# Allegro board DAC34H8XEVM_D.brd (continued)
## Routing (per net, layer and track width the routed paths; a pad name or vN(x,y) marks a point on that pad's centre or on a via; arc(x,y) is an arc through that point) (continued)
DB3N: length 67.1
  BOTTOM w0.127: U1.P4 42.44,62.14 42.44,61.77
  BOTTOM w0.152: 42.44,61.77 42.44,59.27 37.25,54.08 36.96,54.08 36.12,53.24 35.7,53.24 35.41,53.54 35.41,54.78 35.27,54.91 35.08,54.91 34.95,54.78 34.95,53.54 34.65,53.24 34.23,53.24 33.93,53.54 33.93,54.78 33.8,54.91 33.61,54.91 33.48,54.78 33.48,53.54 33.18,53.24 32.76,53.24 32.46,53.54 32.46,54.78 32.33,54.91 32.14,54.91 32,54.78 32,53.54 31.7,53.24 31.28,53.24 30.99,53.54 30.99,54.78 30.85,54.91 30.66,54.91 30.53,54.78 30.53,53.54 30.23,53.24 29.81,53.24 29.51,53.54 29.51,54.78 29.38,54.91 29.19,54.91 29.06,54.78 29.06,53.54 28.76,53.24 28.34,53.24 28.04,53.54 28.04,54.78 27.91,54.91 27.72,54.91 27.58,54.78 27.58,53.54 27.29,53.24 26.86,53.24 26.57,53.54 26.57,54.78 26.43,54.91 26.24,54.91 26.11,54.78 26.11,53.54 25.81,53.24 25.39,53.24 25.09,53.54 25.09,54.78 24.96,54.91 24.77,54.91 24.64,54.78 24.64,53.54 24.34,53.24 23.92,53.24 23.62,53.54 23.62,54.78 23.49,54.91 23.3,54.91 23.16,54.78 23.16,53.54 22.87,53.24 22.44,53.24 22.15,53.54 22.15,54.78 22.01,54.91 21.82,54.91 21.69,54.78 21.69,53.54 21.39,53.24 20.97,53.24 20.67,53.54 20.67,54.78 20.54,54.91 20.35,54.91 20.22,54.78 20.22,53.54 19.92,53.24 19.5,53.24 18.66,54.08 18.53,54.08 15.4,57.2 14.99,57.2 v2(14.98,57.2) 14.88,57.1 13.96,57.1 13.88,57.02 J13.148
DB3P: length 67.7
  BOTTOM w0.127: 42.15,61.69 42.15,62.64 U1.N4
  BOTTOM w0.152: J13.146 13.88,57.52 13.97,57.61 14.71,57.61 14.78,57.68 15.43,57.68 15.44,57.68 v2(15.44,57.68) 15.65,57.48 15.65,57.35 18.64,54.36 18.78,54.36 19.61,53.52 19.8,53.52 19.94,53.65 19.94,54.9 20.23,55.19 20.66,55.19 20.95,54.9 20.95,53.65 21.09,53.52 21.28,53.52 21.41,53.65 21.41,54.9 21.71,55.19 22.13,55.19 22.43,54.9 22.43,53.65 22.56,53.52 22.75,53.52 22.88,53.65 22.88,54.9 23.18,55.19 23.6,55.19 23.9,54.9 23.9,53.65 24.03,53.52 24.22,53.52 24.36,53.65 24.36,54.9 24.65,55.19 25.08,55.19 25.37,54.9 25.37,53.65 25.51,53.52 25.7,53.52 25.83,53.65 25.83,54.9 26.13,55.19 26.55,55.19 26.85,54.9 26.85,53.65 26.98,53.52 27.17,53.52 27.3,53.65 27.3,54.9 27.6,55.19 28.02,55.19 28.32,54.9 28.32,53.65 28.45,53.52 28.64,53.52 28.78,53.65 28.78,54.9 29.07,55.19 29.49,55.19 29.79,54.9 29.79,53.65 29.93,53.52 30.12,53.52 30.25,53.65 30.25,54.9 30.55,55.19 30.97,55.19 31.27,54.9 31.27,53.65 31.4,53.52 31.59,53.52 31.72,53.65 31.72,54.9 32.02,55.19 32.44,55.19 32.74,54.9 32.74,53.65 32.87,53.52 33.06,53.52 33.2,53.65 33.2,54.9 33.49,55.19 33.91,55.19 34.21,54.9 34.21,53.65 34.35,53.52 34.54,53.52 34.67,53.65 34.67,54.9 34.97,55.19 35.39,55.19 35.69,54.9 35.69,53.65 35.82,53.52 36.01,53.52 36.85,54.36 37.13,54.36 42.16,59.39 42.16,61.67 42.15,61.69
DB4N: length 66.9
  BOTTOM w0.127: 41.71,61.77 41.71,62.2 U1.P3
  BOTTOM w0.152: 41.71,61.77 41.71,59.65 38.34,56.29 37.15,56.29 36.85,56.58 36.85,56.97 36.72,57.1 36.53,57.1 36.4,56.97 36.4,55.77 36.1,55.47 35.68,55.47 35.38,55.77 35.38,56.97 35.25,57.1 35.06,57.1 34.92,56.97 34.92,55.77 34.63,55.47 34.21,55.47 33.91,55.77 33.91,56.97 33.77,57.1 33.59,57.1 33.45,56.97 33.45,55.77 33.15,55.47 32.73,55.47 32.44,55.77 32.44,56.97 32.3,57.1 32.11,57.1 31.98,56.97 31.98,55.77 31.68,55.47 31.26,55.47 30.96,55.77 30.96,56.97 30.83,57.1 30.64,57.1 30.5,56.97 30.5,55.77 30.21,55.47 29.79,55.47 29.49,55.77 29.49,56.97 29.36,57.1 29.17,57.1 29.03,56.97 29.03,55.77 28.73,55.47 28.31,55.47 28.02,55.77 28.02,56.97 27.88,57.1 27.69,57.1 27.56,56.97 27.56,55.77 27.26,55.47 26.84,55.47 26.54,55.77 26.54,56.97 26.41,57.1 26.22,57.1 26.09,56.97 26.09,55.77 25.79,55.47 25.37,55.47 25.07,55.77 25.07,56.97 24.94,57.1 24.75,57.1 24.61,56.97 24.61,55.77 24.31,55.47 23.89,55.47 23.6,55.77 23.6,56.97 23.46,57.1 23.27,57.1 23.14,56.97 23.14,55.77 22.84,55.47 22.42,55.47 22.12,55.77 22.12,56.97 21.99,57.1 21.8,57.1 21.67,56.97 21.67,55.77 21.37,55.47 20.95,55.47 20.65,55.77 20.65,56.97 20.52,57.1 20.33,57.1 20.19,56.97 20.19,55.77 19.9,55.47 19.47,55.47 19.18,55.77 19.18,56.97 19.04,57.1 18.85,57.1 18.72,56.97 18.72,56.58 18.42,56.29 17.74,56.29 15.51,58.52 15.32,58.52 15.32,58.52 v2(14.96,58.52) 14.88,58.6 13.96,58.6 13.88,58.52 J13.142
DB4P: length 67.5
  BOTTOM w0.127: 41.35,61.8 41.35,62.64 U1.N3
  BOTTOM w0.152: J13.140 13.88,59.02 13.95,58.95 14.71,58.95 14.76,59 15.42,59 v2(15.42,59) 17.86,56.57 18.31,56.57 18.44,56.7 18.44,57.08 18.74,57.38 19.16,57.38 19.46,57.08 19.46,55.89 19.59,55.75 19.78,55.75 19.91,55.89 19.91,57.08 20.21,57.38 20.63,57.38 20.93,57.08 20.93,55.89 21.06,55.75 21.25,55.75 21.39,55.89 21.39,57.08 21.68,57.38 22.1,57.38 22.4,57.08 22.4,55.89 22.54,55.75 22.73,55.75 22.86,55.89 22.86,57.08 23.16,57.38 23.58,57.38 23.88,57.08 23.88,55.89 24.01,55.75 24.2,55.75 24.33,55.89 24.33,57.08 24.63,57.38 25.05,57.38 25.35,57.08 25.35,55.89 25.48,55.75 25.67,55.75 25.81,55.89 25.81,57.08 26.1,57.38 26.52,57.38 26.82,57.08 26.82,55.89 26.96,55.75 27.15,55.75 27.28,55.89 27.28,57.08 27.58,57.38 28,57.38 28.3,57.08 28.3,55.89 28.43,55.75 28.62,55.75 28.75,55.89 28.75,57.08 29.05,57.38 29.47,57.38 29.77,57.08 29.77,55.89 29.9,55.75 30.09,55.75 30.23,55.89 30.23,57.08 30.52,57.38 30.94,57.38 31.24,57.08 31.24,55.89 31.38,55.75 31.56,55.75 31.7,55.89 31.7,57.08 32,57.38 32.42,57.38 32.71,57.08 32.71,55.89 32.85,55.75 33.04,55.75 33.17,55.89 33.17,57.08 33.47,57.38 33.89,57.38 34.19,57.08 34.19,55.89 34.32,55.75 34.51,55.75 34.65,55.89 34.65,57.08 34.94,57.38 35.36,57.38 35.66,57.08 35.66,55.89 35.79,55.75 35.98,55.75 36.12,55.89 36.12,57.08 36.42,57.38 36.84,57.38 37.13,57.08 37.13,56.7 37.27,56.57 38.23,56.57 41.43,59.77 41.43,61.72 41.35,61.8
DB5N: length 67
  BOTTOM w0.127: 40.78,61.43 40.94,61.59 U1.P2
  BOTTOM w0.152: 40.78,61.43 40.08,60.73 38.06,60.73 36.82,59.49 35.28,59.49 34.93,59.14 34.93,58.26 34.63,57.96 34.21,57.96 33.92,58.26 33.92,59.71 33.78,59.84 33.59,59.84 33.46,59.71 33.46,58.26 33.16,57.96 32.74,57.96 32.44,58.26 32.44,59.71 32.31,59.84 32.12,59.84 31.99,59.71 31.99,58.26 31.69,57.96 31.27,57.96 30.97,58.26 30.97,59.71 30.84,59.84 30.65,59.84 30.51,59.71 30.51,58.26 30.21,57.96 29.79,57.96 29.5,58.26 29.5,59.71 29.36,59.84 29.17,59.84 29.04,59.71 29.04,58.26 28.74,57.96 28.32,57.96 28.02,58.26 28.02,59.71 27.89,59.84 27.7,59.84 27.57,59.71 27.57,58.26 27.27,57.96 26.85,57.96 26.55,58.26 26.55,59.71 26.42,59.84 26.23,59.84 26.09,59.71 26.09,58.26 25.8,57.96 25.37,57.96 25.08,58.26 25.08,59.71 24.94,59.84 24.75,59.84 24.62,59.71 24.62,58.26 24.32,57.96 23.9,57.96 23.6,58.26 23.6,59.71 23.47,59.84 23.28,59.84 23.15,59.71 23.15,58.26 22.85,57.96 22.43,57.96 22.13,58.26 22.13,59.71 22,59.84 21.81,59.84 21.67,59.71 21.67,58.26 21.38,57.96 20.95,57.96 20.66,58.26 20.66,59.71 20.52,59.84 20.33,59.84 20.2,59.71 20.2,58.26 19.9,57.96 19.48,57.96 19.18,58.26 19.18,59.71 19.05,59.84 18.86,59.84 18.73,59.71 18.73,58.26 18.43,57.96 18.01,57.96 17.71,58.26 17.71,58.77 17.58,58.9 17.46,58.9 16.11,60.25 15.82,60.25 v2(15.57,59.99) 15.52,60.05 14.94,60.05 14.89,60.1 13.96,60.1 13.88,60.02 J13.136
DB5P: length 67.3
  BOTTOM w0.127: 40.54,61.77 40.54,62.64 U1.N2
  BOTTOM w0.152: 40.54,61.77 40.54,61.58 39.97,61.01 37.95,61.01 36.7,59.77 35.16,59.77 34.65,59.25 34.65,58.38 34.52,58.24 34.33,58.24 34.2,58.38 34.2,59.82 33.9,60.12 33.48,60.12 33.18,59.82 33.18,58.38 33.05,58.24 32.86,58.24 32.72,58.38 32.72,59.82 32.42,60.12 32,60.12 31.71,59.82 31.71,58.38 31.57,58.24 31.38,58.24 31.25,58.38 31.25,59.82 30.95,60.12 30.53,60.12 30.23,59.82 30.23,58.38 30.1,58.24 29.91,58.24 29.78,58.38 29.78,59.82 29.48,60.12 29.06,60.12 28.76,59.82 28.76,58.38 28.63,58.24 28.44,58.24 28.3,58.38 28.3,59.82 28.01,60.12 27.58,60.12 27.29,59.82 27.29,58.38 27.15,58.24 26.96,58.24 26.83,58.38 26.83,59.82 26.53,60.12 26.11,60.12 25.81,59.82 25.81,58.38 25.68,58.24 25.49,58.24 25.36,58.38 25.36,59.82 25.06,60.12 24.64,60.12 24.34,59.82 24.34,58.38 24.21,58.24 24.02,58.24 23.88,58.38 23.88,59.82 23.59,60.12 23.16,60.12 22.87,59.82 22.87,58.38 22.73,58.24 22.54,58.24 22.41,58.38 22.41,59.82 22.11,60.12 21.69,60.12 21.39,59.82 21.39,58.38 21.26,58.24 21.07,58.24 20.94,58.38 20.94,59.82 20.64,60.12 20.22,60.12 19.92,59.82 19.92,58.38 19.79,58.24 19.6,58.24 19.46,58.38 19.46,59.82 19.17,60.12 18.74,60.12 18.45,59.82 18.45,58.38 18.31,58.24 18.12,58.24 17.99,58.38 17.99,58.88 17.69,59.18 17.58,59.18 16.23,60.53 v2(15.14,60.53) 15.06,60.45 13.95,60.45 13.88,60.52 J13.134
DB6N: length 67
  BOTTOM w0.127: U1.P1 40.13,62.24 39.85,62.51 39.1,62.51 39.09,62.5 39.06,62.5
  BOTTOM w0.152: J13.130 13.88,61.52 13.96,61.6 14.77,61.6 v2(15.01,61.37) 16.15,61.37 16.36,61.57 17.15,61.57 17.45,61.87 17.45,62.4 17.58,62.53 17.77,62.53 17.9,62.4 17.9,60.9 18.2,60.6 18.62,60.6 18.92,60.9 18.92,62.4 19.05,62.53 19.24,62.53 19.38,62.4 19.38,60.9 19.67,60.6 20.09,60.6 20.39,60.9 20.39,62.4 20.53,62.53 20.72,62.53 20.85,62.4 20.85,60.9 21.15,60.6 21.57,60.6 21.87,60.9 21.87,62.4 22,62.53 22.19,62.53 22.32,62.4 22.32,60.9 22.62,60.6 23.04,60.6 23.34,60.9 23.34,62.4 23.47,62.53 23.66,62.53 23.8,62.4 23.8,60.9 24.09,60.6 24.51,60.6 24.81,60.9 24.81,62.4 24.95,62.53 25.13,62.53 25.27,62.4 25.27,60.9 25.57,60.6 25.99,60.6 26.28,60.9 26.28,62.4 26.42,62.53 26.61,62.53 26.74,62.4 26.74,60.9 27.04,60.6 27.46,60.6 27.76,60.9 27.76,62.4 27.89,62.53 28.08,62.53 28.22,62.4 28.22,60.9 28.51,60.6 28.93,60.6 29.23,60.9 29.23,62.4 29.36,62.53 29.55,62.53 29.69,62.4 29.69,60.9 29.99,60.6 30.41,60.6 30.7,60.9 30.7,62.4 30.84,62.53 31.03,62.53 31.16,62.4 31.16,60.9 31.46,60.6 31.88,60.6 32.18,60.9 32.18,62.4 32.31,62.53 32.5,62.53 32.63,62.4 32.63,60.9 32.93,60.6 33.35,60.6 33.65,60.9 33.65,62.4 33.78,62.53 33.97,62.53 34.11,62.4 34.11,60.9 34.41,60.6 34.83,60.6 35.12,60.9 35.12,61.44 35.26,61.57 36.96,61.57 37.89,62.5 39.06,62.5
DB6P: length 67
  BOTTOM w0.127: U1.N1 40.14,63.02 39.88,62.76 39.18,62.76 39.17,62.78 39.06,62.78
  BOTTOM w0.152: 39.06,62.78 37.77,62.78 36.84,61.85 35.14,61.85 34.84,61.55 34.84,61.02 34.71,60.88 34.52,60.88 34.39,61.02 34.39,62.52 34.09,62.81 33.67,62.81 33.37,62.52 33.37,61.02 33.24,60.88 33.05,60.88 32.91,61.02 32.91,62.52 32.62,62.81 32.2,62.81 31.9,62.52 31.9,61.02 31.76,60.88 31.57,60.88 31.44,61.02 31.44,62.52 31.14,62.81 30.72,62.81 30.42,62.52 30.42,61.02 30.29,60.88 30.1,60.88 29.97,61.02 29.97,62.52 29.67,62.81 29.25,62.81 28.95,62.52 28.95,61.02 28.82,60.88 28.63,60.88 28.49,61.02 28.49,62.52 28.2,62.81 27.78,62.81 27.48,62.52 27.48,61.02 27.34,60.88 27.16,60.88 27.02,61.02 27.02,62.52 26.72,62.81 26.3,62.81 26.01,62.52 26.01,61.02 25.87,60.88 25.68,60.88 25.55,61.02 25.55,62.52 25.25,62.81 24.83,62.81 24.53,62.52 24.53,61.02 24.4,60.88 24.21,60.88 24.07,61.02 24.07,62.52 23.78,62.81 23.36,62.81 23.06,62.52 23.06,61.02 22.93,60.88 22.74,60.88 22.6,61.02 22.6,62.52 22.3,62.81 21.88,62.81 21.59,62.52 21.59,61.02 21.45,60.88 21.26,60.88 21.13,61.02 21.13,62.52 20.83,62.81 20.41,62.81 20.11,62.52 20.11,61.02 19.98,60.88 19.79,60.88 19.66,61.02 19.66,62.52 19.36,62.81 18.94,62.81 18.64,62.52 18.64,61.02 18.51,60.88 18.32,60.88 18.18,61.02 18.18,62.52 17.88,62.81 17.46,62.81 17.17,62.52 17.17,61.98 17.03,61.85 16.24,61.85 16.04,61.65 15.7,61.65 v2(15.49,61.85) 14.99,61.85 14.89,61.95 13.95,61.95 13.88,62.02 J13.128
DB7N: length 66.9
  BOTTOM w0.127: U1.M1 40.1,63.88 39.82,63.88 39.79,63.86
  BOTTOM w0.152: 39.79,63.86 35.75,63.86 35.29,64.31 35.29,64.31 34.45,65.15 34.13,65.15 33.95,64.97 33.95,63.59 33.65,63.3 33.23,63.3 32.93,63.59 32.93,65.19 32.8,65.33 32.61,65.33 32.47,65.19 32.47,63.59 32.18,63.3 31.76,63.3 31.46,63.59 31.46,65.19 31.33,65.33 31.14,65.33 31,65.19 31,63.59 30.7,63.3 30.28,63.3 29.99,63.59 29.99,65.19 29.85,65.33 29.66,65.33 29.53,65.19 29.53,63.59 29.23,63.3 28.81,63.3 28.51,63.59 28.51,65.19 28.38,65.33 28.19,65.33 28.06,65.19 28.06,63.59 27.76,63.3 27.34,63.3 27.04,63.59 27.04,65.19 26.91,65.33 26.72,65.33 26.58,65.19 26.58,63.59 26.28,63.3 25.86,63.3 25.57,63.59 25.57,65.19 25.43,65.33 25.24,65.33 25.11,65.19 25.11,63.59 24.81,63.3 24.39,63.3 24.09,63.59 24.09,65.19 23.96,65.33 23.77,65.33 23.64,65.19 23.64,63.59 23.34,63.3 22.92,63.3 22.62,63.59 22.62,65.19 22.49,65.33 22.3,65.33 22.16,65.19 22.16,63.59 21.87,63.3 21.44,63.3 21.15,63.59 21.15,65.19 21.01,65.33 20.82,65.33 20.69,65.19 20.69,63.59 20.39,63.3 19.97,63.3 19.67,63.59 19.67,65.19 19.54,65.33 19.35,65.33 19.22,65.19 19.22,63.59 18.92,63.3 18.5,63.3 18.2,63.59 18.2,65.19 18.07,65.33 17.88,65.33 17.74,65.19 17.74,64.99 15.89,63.14 15.85,63.14 15.74,63.04 14.93,63.04 v2(14.91,63.02) 13.88,63.02 J13.124
DB7P: length 67.8
  BOTTOM w0.127: U1.M2 40.55,64.23 39.77,64.23 39.67,64.14
  BOTTOM w0.152: J13.122 13.88,63.52 v2(15.36,63.52) 15.38,63.52 15.48,63.42 15.76,63.42 17.46,65.12 17.46,65.31 17.76,65.61 18.18,65.61 18.48,65.31 18.48,63.71 18.61,63.58 18.8,63.58 18.94,63.71 18.94,65.31 19.23,65.61 19.66,65.61 19.95,65.31 19.95,63.71 20.09,63.58 20.28,63.58 20.41,63.71 20.41,65.31 20.71,65.61 21.13,65.61 21.43,65.31 21.43,63.71 21.56,63.58 21.75,63.58 21.88,63.71 21.88,65.31 22.18,65.61 22.6,65.61 22.9,65.31 22.9,63.71 23.03,63.58 23.22,63.58 23.36,63.71 23.36,65.31 23.65,65.61 24.07,65.61 24.37,65.31 24.37,63.71 24.51,63.58 24.7,63.58 24.83,63.71 24.83,65.31 25.13,65.61 25.55,65.61 25.85,65.31 25.85,63.71 25.98,63.58 26.17,63.58 26.3,63.71 26.3,65.31 26.6,65.61 27.02,65.61 27.32,65.31 27.32,63.71 27.45,63.58 27.64,63.58 27.78,63.71 27.78,65.31 28.07,65.61 28.49,65.61 28.79,65.31 28.79,63.71 28.93,63.58 29.12,63.58 29.25,63.71 29.25,65.31 29.55,65.61 29.97,65.61 30.27,65.31 30.27,63.71 30.4,63.58 30.59,63.58 30.72,63.71 30.72,65.31 31.02,65.61 31.44,65.61 31.74,65.31 31.74,63.71 31.87,63.58 32.06,63.58 32.2,63.71 32.2,65.31 32.49,65.61 32.91,65.61 33.21,65.31 33.21,63.71 33.35,63.58 33.53,63.58 33.67,63.71 33.67,65.09 34.01,65.43 34.57,65.43 35.4,64.59 35.41,64.59 35.86,64.14 39.67,64.14
DB8N: length 67.1
  L6_PWR w0.127: U1.M3 41.62,63.84 41.23,63.44 39.99,63.44 39.75,63.2 39.75,62.87 39.59,62.71 36.57,62.71 36.29,62.44 36.29,62 36.16,61.87 35.99,61.87 35.86,62 35.86,63.28 35.58,63.55 35.19,63.55 34.92,63.28 34.92,62 34.79,61.87 34.61,61.87 34.49,62 34.49,63.28 34.21,63.55 33.82,63.55 33.55,63.28 33.55,62 33.42,61.87 33.24,61.87 33.12,62 33.12,63.28 32.84,63.55 32.45,63.55 32.18,63.28 32.18,62 32.05,61.87 31.87,61.87 31.74,62 31.74,63.28 31.47,63.55 31.08,63.55 30.8,63.28 30.8,62 30.68,61.87 30.5,61.87 30.37,62 30.37,63.28 30.1,63.55 29.71,63.55 29.43,63.28 29.43,62 29.31,61.87 29.13,61.87 29,62 29,63.28 28.73,63.55 28.34,63.55 28.06,63.28 28.06,62 27.94,61.87 27.76,61.87 27.63,62 27.63,63.28 27.35,63.55 26.97,63.55 26.69,63.28 26.69,62 26.56,61.87 26.38,61.87 26.26,62 26.26,63.28 25.98,63.55 25.59,63.55 25.32,63.28 25.32,62 25.19,61.87 25.01,61.87 24.89,62 24.89,63.28 24.61,63.55 24.22,63.55 23.95,63.28 23.95,62 23.82,61.87 23.64,61.87 23.52,62 23.52,63.28 23.24,63.55 22.85,63.55 22.58,63.28 22.58,62 22.45,61.87 22.27,61.87 22.14,62 22.14,62.44 21.87,62.71 20.35,62.71 13.67,69.39 13.67,71.09 13.95,71.37 14.63,71.37 14.84,71.16 15.51,71.16 v2(15.57,71.22)
  BOTTOM w0.152: J13.112 13.88,71.04 13.96,71.12 15.47,71.12 v2(15.57,71.22)
DB8P: length 67.6
  L6_PWR w0.127: v2(15.04,71.63) 13.84,71.63 13.41,71.2 13.41,69.29 20.24,62.46 21.76,62.46 21.89,62.33 21.89,61.9 22.16,61.62 22.55,61.62 22.83,61.9 22.83,63.17 22.96,63.3 23.13,63.3 23.26,63.17 23.26,61.9 23.54,61.62 23.93,61.62 24.2,61.9 24.2,63.17 24.33,63.3 24.51,63.3 24.63,63.17 24.63,61.9 24.91,61.62 25.3,61.62 25.57,61.9 25.57,63.17 25.7,63.3 25.88,63.3 26,63.17 26,61.9 26.28,61.62 26.67,61.62 26.94,61.9 26.94,63.17 27.07,63.3 27.25,63.3 27.38,63.17 27.38,61.9 27.65,61.62 28.04,61.62 28.32,61.9 28.32,63.17 28.44,63.3 28.62,63.3 28.75,63.17 28.75,61.9 29.02,61.62 29.41,61.62 29.69,61.9 29.69,63.17 29.81,63.3 29.99,63.3 30.12,63.17 30.12,61.9 30.39,61.62 30.78,61.62 31.06,61.9 31.06,63.17 31.19,63.3 31.36,63.3 31.49,63.17 31.49,61.9 31.77,61.62 32.16,61.62 32.43,61.9 32.43,63.17 32.56,63.3 32.74,63.3 32.86,63.17 32.86,61.9 33.14,61.62 33.53,61.62 33.8,61.9 33.8,63.17 33.93,63.3 34.11,63.3 34.23,63.17 34.23,61.9 34.51,61.62 34.9,61.62 35.17,61.9 35.17,63.17 35.3,63.3 35.48,63.3 35.61,63.17 35.61,61.9 35.88,61.62 36.27,61.62 36.55,61.9 36.55,62.33 36.67,62.46 39.69,62.46 39.87,62.63 40.76,62.63 40.78,62.64 41.1,62.64 41.33,62.87 41.33,63.19 41.58,63.43 41.89,63.43 42.3,63.84 U1.M4
  BOTTOM w0.152: J13.110 13.88,71.54 14.95,71.54 v2(15.04,71.63)
DB9N: length 66.9
  BOTTOM w0.127: U1.L1 40.01,64.76 39.82,64.76
  BOTTOM w0.152: 39.82,64.76 36.54,64.76 31.56,69.75 30.52,69.75 28.05,72.21 27.28,72.21 27.15,72.08 27.15,70.93 26.85,70.64 26.43,70.64 26.13,70.93 26.13,73.65 26,73.79 25.81,73.79 25.68,73.65 25.68,70.93 25.38,70.64 24.96,70.64 24.66,70.93 24.66,73.65 24.53,73.79 24.34,73.79 24.2,73.65 24.2,70.93 23.9,70.64 23.48,70.64 23.19,70.93 23.19,73.65 23.05,73.79 22.86,73.79 22.73,73.65 22.73,70.93 22.43,70.64 22.01,70.64 21.71,70.93 21.71,73.65 21.58,73.79 21.39,73.79 21.26,73.65 21.26,70.93 20.96,70.64 20.54,70.64 20.24,70.93 20.24,73.65 20.11,73.79 19.92,73.79 19.78,73.65 19.78,70.93 19.48,70.64 19.06,70.64 18.77,70.93 18.77,73.65 18.63,73.79 18.44,73.79 18.31,73.65 18.31,70.93 18.01,70.64 17.59,70.64 17.29,70.93 17.29,71.66 16.38,72.57 15.92,72.57 15.69,72.34 v2(15.04,72.34) 14.84,72.54 13.88,72.54 J13.106
DB9P: length 67.7
  BOTTOM w0.127: U1.L2 40.94,64.67 40.57,65.04 39.78,65.04
  BOTTOM w0.152: 39.78,65.04 36.66,65.04 31.67,70.03 30.63,70.03 28.17,72.49 27.17,72.49 26.87,72.19 26.87,71.05 26.74,70.92 26.55,70.92 26.41,71.05 26.41,73.77 26.11,74.07 25.69,74.07 25.4,73.77 25.4,71.05 25.26,70.92 25.07,70.92 24.94,71.05 24.94,73.77 24.64,74.07 24.22,74.07 23.92,73.77 23.92,71.05 23.79,70.92 23.6,70.92 23.47,71.05 23.47,73.77 23.17,74.07 22.75,74.07 22.45,73.77 22.45,71.05 22.32,70.92 22.13,70.92 21.99,71.05 21.99,73.77 21.69,74.07 21.27,74.07 20.98,73.77 20.98,71.05 20.84,70.92 20.65,70.92 20.52,71.05 20.52,73.77 20.22,74.07 19.8,74.07 19.5,73.77 19.5,71.05 19.37,70.92 19.18,70.92 19.05,71.05 19.05,73.77 18.75,74.07 18.33,74.07 18.03,73.77 18.03,71.05 17.9,70.92 17.71,70.92 17.57,71.05 17.57,71.77 16.5,72.85 15.81,72.85 15.79,72.83 v2(15.51,72.83) 14.78,72.83 14.64,72.97 13.94,72.97 13.88,73.04 J13.104
DB10N: length 67
  L6_PWR w0.127: U1.L3 41.5,64.64 41.1,64.24 39.98,64.24 39.75,64.47 39.75,64.85 39.62,64.97 24.54,64.97 23.57,65.94 23.4,65.94 22.72,65.26 22.33,65.26 22.05,65.53 22.05,65.92 23.69,67.56 23.69,67.74 23.57,67.87 23.39,67.87 21.75,66.23 21.36,66.23 21.08,66.5 21.08,66.89 22.72,68.53 22.72,68.71 22.6,68.84 22.42,68.84 20.78,67.2 20.39,67.2 20.11,67.47 20.11,67.86 21.75,69.5 21.75,69.68 21.63,69.81 21.45,69.81 19.81,68.17 19.42,68.17 19.14,68.44 19.14,68.83 20.78,70.47 20.78,70.65 20.66,70.78 20.48,70.78 18.84,69.14 18.45,69.14 18.17,69.41 18.17,69.8 19.81,71.44 19.81,71.62 19.69,71.75 19.51,71.75 17.87,70.11 17.48,70.11 17.2,70.38 17.2,70.77 18.84,72.42 18.84,72.59 18.72,72.72 18.54,72.72 16.9,71.08 16.51,71.08 16.23,71.35 16.23,71.74 17.87,73.39 17.87,73.56 17.75,73.69 17.57,73.69 16.89,73.01 16.5,73.01 15.47,74.04 v2(14.93,74.04)
  BOTTOM w0.152: v2(14.93,74.04) 14.85,74.12 13.96,74.12 13.88,74.04 J13.100
DB10P: length 67.5
  L6_PWR w0.127: v2(15.37,74.55) 15.37,74.5 16.6,73.27 16.78,73.27 17.46,73.94 17.85,73.94 18.13,73.67 18.13,73.28 16.48,71.64 16.48,71.46 16.61,71.33 16.79,71.33 18.43,72.97 18.82,72.97 19.1,72.7 19.1,72.31 17.45,70.67 17.45,70.49 17.58,70.36 17.76,70.36 19.4,72 19.79,72 20.07,71.73 20.07,71.34 18.43,69.7 18.43,69.52 18.55,69.39 18.73,69.39 20.37,71.03 20.76,71.03 21.04,70.76 21.04,70.37 19.4,68.73 19.4,68.55 19.52,68.42 19.7,68.42 21.34,70.06 21.73,70.06 22.01,69.79 22.01,69.4 20.37,67.76 20.37,67.58 20.49,67.45 20.67,67.45 22.31,69.09 22.7,69.09 22.98,68.82 22.98,68.43 21.34,66.79 21.34,66.61 21.46,66.48 21.64,66.48 23.28,68.12 23.67,68.12 23.95,67.85 23.95,67.46 22.31,65.82 22.31,65.64 22.43,65.51 22.61,65.51 23.29,66.19 23.68,66.19 24.64,65.23 39.73,65.23 39.93,65.03 41.9,65.03 42.3,64.64 U1.L4
  BOTTOM w0.152: 13.88,74.54 13.88,74.54 ; 13.88,74.54 J13.98 ; 13.88,74.54 13.97,74.45 14.66,74.45 14.73,74.52 15.34,74.52 v2(15.37,74.55)
DB11N: length 66.8
  BOTTOM w0.127: 39.85,65.48 40.09,65.48 U1.K1
  BOTTOM w0.152: J13.94 13.88,75.54 13.91,75.51 14.83,75.51 v2(15.11,75.79) 15.14,75.82 15.75,75.82 15.9,75.67 16.22,75.67 16.54,75.98 16.54,77.02 16.75,77.24 17.18,77.24 17.39,77.03 17.39,74.85 17.69,74.55 18.11,74.55 18.41,74.85 18.41,78.12 18.54,78.26 18.73,78.26 18.87,78.12 18.87,74.85 19.17,74.55 19.59,74.55 19.88,74.85 19.88,78.12 20.02,78.26 20.21,78.26 20.34,78.12 20.34,74.85 20.64,74.55 21.06,74.55 21.36,74.85 21.36,78.12 21.49,78.26 21.68,78.26 21.81,78.12 21.81,74.85 22.11,74.55 22.53,74.55 22.83,74.85 22.83,78.12 22.96,78.26 23.15,78.26 23.29,78.12 23.29,74.85 23.58,74.55 24.01,74.55 24.3,74.85 24.3,78.12 24.44,78.26 24.63,78.26 24.76,78.12 24.76,77.59 33.83,68.52 34.96,68.52 37.8,65.68 39.65,65.68 39.85,65.48
DB11P: length 67.6
  BOTTOM w0.127: 39.89,65.84 40.46,65.84 40.86,65.44 U1.K2
  BOTTOM w0.152: J13.92 13.88,76.04 13.92,76 14.63,76 14.91,76.28 15.52,76.28 v2(15.54,76.3) 15.72,76.12 16.03,76.12 16.26,76.35 16.26,77.14 16.64,77.52 17.3,77.52 17.67,77.14 17.67,74.96 17.81,74.83 18,74.83 18.13,74.96 18.13,78.24 18.43,78.54 18.85,78.54 19.15,78.24 19.15,74.96 19.28,74.83 19.47,74.83 19.6,74.96 19.6,78.24 19.9,78.54 20.32,78.54 20.62,78.24 20.62,74.96 20.75,74.83 20.94,74.83 21.08,74.96 21.08,78.24 21.38,78.54 21.8,78.54 22.09,78.24 22.09,74.96 22.23,74.83 22.42,74.83 22.55,74.96 22.55,78.24 22.85,78.54 23.27,78.54 23.57,78.24 23.57,74.96 23.7,74.83 23.89,74.83 24.02,74.96 24.02,78.24 24.32,78.54 24.74,78.54 25.04,78.24 25.04,77.7 33.94,68.8 35.07,68.8 37.91,65.96 39.77,65.96 39.89,65.84
DB12N: length 66.9
  L6_PWR w0.127: U1.K3 41.59,65.59 41.47,65.59 41.22,65.84 39.98,65.84 39.75,66.07 39.75,66.22 39.45,66.52 33.67,66.52 33.28,66.13 30.77,66.13 29.36,67.54 29.36,68.6 29.24,68.72 29.06,68.72 27.82,67.49 27.43,67.49 27.16,67.76 27.16,68.15 28.39,69.39 28.39,69.57 28.27,69.69 28.09,69.69 26.85,68.46 26.46,68.46 26.19,68.73 26.19,69.12 27.42,70.36 27.42,70.54 27.3,70.66 27.12,70.66 25.88,69.43 25.49,69.43 25.22,69.7 25.22,70.09 26.45,71.33 26.45,71.51 26.33,71.63 26.15,71.63 24.91,70.4 24.52,70.4 24.25,70.67 24.25,71.06 25.48,72.3 25.48,72.48 25.36,72.6 25.18,72.6 23.94,71.37 23.55,71.37 23.28,71.64 23.28,72.03 24.51,73.27 24.51,73.45 24.39,73.57 24.21,73.57 22.97,72.34 22.58,72.34 22.31,72.61 22.31,73 23.54,74.24 23.54,74.42 23.42,74.55 23.24,74.55 22,73.31 21.61,73.31 21.34,73.58 21.34,73.97 22.57,75.21 22.57,75.39 22.44,75.52 22.27,75.52 21.03,74.28 20.64,74.28 20.37,74.55 20.37,74.94 21.6,76.18 21.6,76.36 21.47,76.49 21.3,76.49 20.06,75.25 19.67,75.25 19.4,75.52 19.4,75.91 19.87,76.39 19.87,76.6 19.33,77.14 15.88,77.14 15.66,76.92 15.07,76.92 v2(15.03,76.89)
  BOTTOM w0.152: v2(15.03,76.89) 14.81,77.11 13.95,77.11 13.88,77.04 J13.88
DB12P: length 67.8
  L6_PWR w0.127: v2(15.47,77.39) 19.43,77.39 20.13,76.7 20.13,76.29 19.65,75.81 19.65,75.63 19.78,75.5 19.95,75.5 21.19,76.74 21.58,76.74 21.86,76.46 21.86,76.08 20.62,74.84 20.62,74.66 20.75,74.53 20.93,74.53 22.16,75.77 22.55,75.77 22.83,75.49 22.83,75.1 21.59,73.87 21.59,73.69 21.72,73.56 21.9,73.56 23.13,74.8 23.52,74.8 23.8,74.52 23.8,74.13 22.56,72.9 22.56,72.72 22.69,72.59 22.87,72.59 24.1,73.83 24.49,73.83 24.77,73.55 24.77,73.16 23.53,71.93 23.53,71.75 23.66,71.62 23.84,71.62 25.07,72.86 25.46,72.86 25.74,72.58 25.74,72.19 24.5,70.96 24.5,70.78 24.63,70.65 24.81,70.65 26.04,71.89 26.43,71.89 26.71,71.61 26.71,71.22 25.47,69.99 25.47,69.81 25.6,69.68 25.78,69.68 27.01,70.92 27.4,70.92 27.68,70.64 27.68,70.25 26.44,69.02 26.44,68.84 26.57,68.71 26.75,68.71 27.98,69.95 28.37,69.95 28.65,69.67 28.65,69.28 27.41,68.05 27.41,67.87 27.54,67.74 27.72,67.74 28.95,68.98 29.34,68.98 29.62,68.7 29.62,67.66 30.9,66.38 33.17,66.38 33.57,66.78 39.57,66.78 39.7,66.64 41.09,66.64 41.33,66.4 41.33,66.09 41.58,65.84 41.89,65.84 42.3,65.44 U1.K4
  BOTTOM w0.152: J13.86 13.88,77.54 13.95,77.47 14.94,77.47 15.01,77.39 v2(15.47,77.39)
DB13N: length 67
  BOTTOM w0.127: U1.J1 40.01,66.37 39.7,66.37
  BOTTOM w0.152: J13.82 13.88,78.54 14.85,78.54 v2(15.01,78.69) 15.03,78.71 15.64,78.71 15.85,78.92 27.12,78.92 27.39,79.19 27.58,79.19 27.71,79.05 27.71,78.86 26.33,77.48 26.33,77.06 26.63,76.76 27.05,76.76 28.43,78.15 28.62,78.15 28.76,78.01 28.76,77.82 27.37,76.44 27.37,76.02 27.67,75.72 28.09,75.72 29.47,77.1 29.66,77.1 29.8,76.97 29.8,76.78 28.42,75.4 28.42,74.98 28.71,74.68 29.13,74.68 30.52,76.06 30.71,76.06 30.84,75.93 30.84,75.74 29.46,74.36 29.46,73.94 29.76,73.64 30.18,73.64 31.56,75.02 31.75,75.02 31.88,74.89 31.88,74.7 30.5,73.31 30.5,72.89 30.8,72.6 31.22,72.6 32.6,73.98 32.79,73.98 32.92,73.84 32.92,73.65 31.54,72.27 31.54,71.85 31.84,71.55 32.26,71.55 33.64,72.94 33.83,72.94 33.97,72.8 33.97,72.61 32.58,71.23 32.58,70.81 32.88,70.51 33.3,70.51 34.68,71.89 34.87,71.89 35.01,71.76 35.01,71.57 33.62,70.19 33.62,69.77 33.92,69.47 34.34,69.47 35.73,70.85 35.92,70.85 36.05,70.72 36.05,69.13 38.63,66.55 39.29,66.55 39.47,66.37 39.7,66.37
DB13P: length 67.8
  BOTTOM w0.127: 39.7,66.65 39.97,66.65 39.98,66.64 40.42,66.64 40.67,66.39 40.79,66.39 U1.J2
  BOTTOM w0.152: J13.80 13.88,79.04 14.67,79.04 14.83,79.2 v2(15.44,79.2) 27.01,79.2 27.28,79.47 27.7,79.47 27.99,79.17 27.99,78.75 26.61,77.37 26.61,77.18 26.75,77.04 26.93,77.04 28.32,78.43 28.74,78.43 29.04,78.13 29.04,77.71 27.65,76.32 27.65,76.13 27.79,76 27.98,76 29.36,77.38 29.78,77.38 30.08,77.09 30.08,76.66 28.69,75.28 28.69,75.09 28.83,74.96 29.02,74.96 30.4,76.34 30.82,76.34 31.12,76.04 31.12,75.62 29.74,74.24 29.74,74.05 29.87,73.92 30.06,73.92 31.44,75.3 31.86,75.3 32.16,75 32.16,74.58 30.78,73.2 30.78,73.01 30.91,72.87 31.1,72.87 32.48,74.26 32.91,74.26 33.2,73.96 33.2,73.54 31.82,72.16 31.82,71.97 31.95,71.83 32.14,71.83 33.53,73.22 33.95,73.22 34.25,72.92 34.25,72.5 32.86,71.11 32.86,70.93 33,70.79 33.19,70.79 34.57,72.17 34.99,72.17 35.29,71.88 35.29,71.46 33.9,70.07 33.9,69.88 34.04,69.75 34.23,69.75 35.61,71.13 36.03,71.13 36.33,70.83 36.33,69.25 38.75,66.83 39.41,66.83 39.59,66.65 39.7,66.65
DB14N: length 66.9
  BOTTOM w0.127: 39.7,67.79 39.7,67.59 39.85,67.44 40.3,67.44 40.55,67.2 40.55,66.87 40.78,66.64 41.22,66.64 41.62,66.24 U1.J3
  BOTTOM w0.152: J13.76 13.88,80.04 13.95,80.11 14.86,80.11 15.28,80.53 v2(15.44,80.53) 15.45,80.54 16.08,80.54 16.76,81.23 17.04,81.23 17.65,81.83 17.65,82.54 17.78,82.68 17.97,82.68 18.11,82.54 18.11,80.08 18.4,79.78 18.82,79.78 19.12,80.08 19.12,82.54 19.26,82.68 19.45,82.68 19.58,82.54 19.58,80.08 19.88,79.78 20.3,79.78 20.6,80.08 20.6,82.54 20.73,82.68 20.92,82.68 21.05,82.54 21.05,80.08 21.35,79.78 21.77,79.78 22.07,80.08 22.07,82.54 22.2,82.68 22.39,82.68 22.53,82.54 22.53,80.08 22.82,79.78 23.24,79.78 23.54,80.08 23.54,82.54 23.68,82.68 23.86,82.68 24,82.54 24,80.08 24.3,79.78 24.72,79.78 25.01,80.08 25.01,82.54 25.15,82.68 25.34,82.68 25.47,82.54 25.47,80.08 25.77,79.78 26.19,79.78 26.49,80.08 26.49,81.1 26.62,81.23 26.92,81.23 37.08,71.07 37.08,69.76 38.89,67.95 39.54,67.95 39.7,67.79
DB14P: length 67.8
  BOTTOM w0.127: 39.67,68.23 40.3,68.23 40.53,68 40.53,67.69 40.79,67.43 41.1,67.43 41.33,67.2 41.33,66.89 41.58,66.64 41.89,66.64 42.3,66.24 U1.J4
  BOTTOM w0.152: 39.67,68.23 39.01,68.23 37.36,69.88 37.36,71.19 27.04,81.51 26.51,81.51 26.21,81.21 26.21,80.19 26.07,80.06 25.89,80.06 25.75,80.19 25.75,82.66 25.45,82.96 25.03,82.96 24.74,82.66 24.74,80.19 24.6,80.06 24.41,80.06 24.28,80.19 24.28,82.66 23.98,82.96 23.56,82.96 23.26,82.66 23.26,80.19 23.13,80.06 22.94,80.06 22.8,80.19 22.8,82.66 22.51,82.96 22.09,82.96 21.79,82.66 21.79,80.19 21.66,80.06 21.47,80.06 21.33,80.19 21.33,82.66 21.03,82.96 20.61,82.96 20.32,82.66 20.32,80.19 20.18,80.06 19.99,80.06 19.86,80.19 19.86,82.66 19.56,82.96 19.14,82.96 18.84,82.66 18.84,80.19 18.71,80.06 18.52,80.06 18.39,80.19 18.39,82.66 18.09,82.96 17.67,82.96 17.37,82.66 17.37,81.95 16.93,81.51 16.65,81.51 16.16,81.03 v2(15.88,81.03) 15.25,81.03 14.77,80.54 13.88,80.54 J13.74
DB15N: length 67
  BOTTOM w0.127: U1.H3 41.82,67.04 42.14,67.35 42.14,67.99 41.89,68.24 41.58,68.24 41.35,68.47 41.35,68.91 41.22,69.04 39.98,69.04 39.42,69.59 39.42,69.67
  BOTTOM w0.152: 39.42,69.67 38.51,70.59 38.51,72.1 38.01,72.6 38.01,73.02 38.34,73.35 38.34,73.54 38.2,73.67 38.01,73.67 37.05,72.71 36.63,72.71 36.33,73 36.33,73.42 37.29,74.39 37.29,74.58 37.16,74.71 36.97,74.71 36.01,73.75 35.59,73.75 35.29,74.05 35.29,74.47 36.25,75.43 36.25,75.62 36.12,75.75 35.93,75.75 34.96,74.79 34.54,74.79 34.25,75.09 34.25,75.51 35.21,76.47 35.21,76.66 35.08,76.8 34.89,76.8 33.92,75.83 33.5,75.83 33.2,76.13 33.2,76.55 34.17,77.52 34.17,77.7 34.03,77.84 33.85,77.84 32.88,76.87 32.46,76.87 32.16,77.17 32.16,77.59 33.13,78.56 33.13,78.75 32.99,78.88 32.8,78.88 31.84,77.92 31.42,77.92 31.12,78.21 31.12,78.63 32.08,79.6 32.08,79.79 31.95,79.92 31.76,79.92 30.8,78.96 30.38,78.96 30.08,79.26 30.08,79.68 31.04,80.64 31.04,80.83 30.91,80.96 30.72,80.96 29.75,80 29.33,80 29.04,80.3 29.04,80.72 30,81.68 30,81.87 29.87,82.01 29.68,82.01 28.71,81.04 28.29,81.04 27.99,81.34 27.99,81.76 28.96,82.72 28.96,82.91 28.82,83.05 27.55,83.05 26.94,83.67 17.55,83.67 16.33,82.45 16.33,82.12 16.05,81.84 15.42,81.84 v2(15.41,81.82) 15.11,81.82 14.9,81.61 13.95,81.61 13.88,81.54 J13.70
DB15P: length 67.8
  BOTTOM w0.127: U1.H4 42.93,67.43 42.93,68 42.7,68.23 42.39,68.23 42.13,68.49 42.13,68.8 41.9,69.03 41.59,69.03 41.33,69.29 41.33,69.6 41.1,69.83 39.66,69.83
  BOTTOM w0.152: J13.68 13.99,82.04 14,82.04 ; 14,82.04 13.88,82.04 ; 14,82.04 14.94,82.04 15.2,82.31 15.83,82.31 v2(15.85,82.32) 15.85,82.36 17.44,83.95 27.05,83.95 27.67,83.33 28.94,83.33 29.24,83.03 29.24,82.61 28.27,81.64 28.27,81.45 28.41,81.32 28.6,81.32 29.56,82.29 29.98,82.29 30.28,81.99 30.28,81.57 29.32,80.6 29.32,80.41 29.45,80.28 29.64,80.28 30.6,81.24 31.02,81.24 31.32,80.95 31.32,80.53 30.36,79.56 30.36,79.37 30.49,79.24 30.68,79.24 31.65,80.2 32.07,80.2 32.36,79.9 32.36,79.48 31.4,78.52 31.4,78.33 31.53,78.19 31.72,78.19 32.69,79.16 33.11,79.16 33.41,78.86 33.41,78.44 32.44,77.48 32.44,77.29 32.58,77.15 32.76,77.15 33.73,78.12 34.15,78.12 34.45,77.82 34.45,77.4 33.48,76.43 33.48,76.25 33.62,76.11 33.81,76.11 34.77,77.08 35.19,77.08 35.49,76.78 35.49,76.36 34.52,75.39 34.52,75.2 34.66,75.07 34.85,75.07 35.81,76.03 36.23,76.03 36.53,75.74 36.53,75.32 35.57,74.35 35.57,74.16 35.7,74.03 35.89,74.03 36.86,74.99 37.28,74.99 37.57,74.69 37.57,74.27 36.61,73.31 36.61,73.12 36.74,72.99 36.93,72.99 37.9,73.95 38.32,73.95 38.62,73.65 38.62,73.23 38.29,72.9 38.29,72.71 38.79,72.21 38.79,70.71 39.66,69.83
DCLK-N: length 37.1
  TOP w0.152: SJP10.1 18.12,69.16 18.3,69.34 18.85,69.34 19.82,70.31 20,70.31 20.14,70.17 20.14,68.73 20.44,68.43 20.86,68.43 21.15,68.73 21.15,70.17 21.29,70.31 21.48,70.31 21.61,70.17 21.61,68.73 21.91,68.43 22.33,68.43 22.63,68.73 22.63,70.17 22.76,70.31 22.95,70.31 23.08,70.17 23.08,68.73 23.38,68.43 23.8,68.43 24.1,68.73 24.1,70.17 24.23,70.31 24.42,70.31 24.56,70.17 24.56,68.73 24.86,68.43 25.28,68.43 25.57,68.73 25.57,70.17 25.71,70.31 25.9,70.31 26.03,70.17 26.03,68.73 26.33,68.43 26.75,68.43 27.05,68.73 27.05,70.17 27.18,70.31 27.37,70.31 27.5,70.17 27.5,68.73 27.8,68.43 28.22,68.43 28.52,68.73 28.52,70.17 28.65,70.31 28.84,70.31 28.98,70.17 28.98,68.73 29.28,68.43 29.7,68.43 29.99,68.73 29.99,69.23 30.13,69.37 30.78,69.37 30.81,69.33 30.81,69.32 30.94,69.19 31.64,69.19 31.78,69.32 31.78,69.36 31.78,69.37 32.36,69.37 SJP12.1
DCLK-P: length 37.2
  TOP w0.152: SJP9.1 16.97,69.42 17.41,69.42 17.63,69.65 18.33,69.65 18.36,69.62 18.73,69.62 19.7,70.59 20.12,70.59 20.42,70.29 20.42,68.84 20.55,68.71 20.74,68.71 20.87,68.84 20.87,70.29 21.17,70.59 21.59,70.59 21.89,70.29 21.89,68.84 22.02,68.71 22.21,68.71 22.35,68.84 22.35,70.29 22.65,70.59 23.07,70.59 23.36,70.29 23.36,68.84 23.5,68.71 23.69,68.71 23.82,68.84 23.82,70.29 24.12,70.59 24.54,70.59 24.84,70.29 24.84,68.84 24.97,68.71 25.16,68.71 25.29,68.84 25.29,70.29 25.59,70.59 26.01,70.59 26.31,70.29 26.31,68.84 26.44,68.71 26.63,68.71 26.77,68.84 26.77,70.29 27.07,70.59 27.49,70.59 27.78,70.29 27.78,68.84 27.92,68.71 28.11,68.71 28.24,68.84 28.24,70.29 28.54,70.59 28.96,70.59 29.26,70.29 29.26,68.84 29.39,68.71 29.58,68.71 29.71,68.84 29.71,69.35 30.01,69.65 31.04,69.65 31.12,69.57 31.12,69.49 SJP11.1
DCLKN: length 88.3
  BOTTOM w0.152: v2(17.98,67.13) 17.68,66.83 17.35,66.83 17.17,67.01 17.17,67.37 17.92,68.12 18.15,68.12 18.49,67.78 18.49,66.7 18.21,66.42 17.31,66.42 15.41,64.52 12.05,64.52 11.94,64.63 11.94,64.96 12.05,65.07 15.2,65.07 15.75,65.62 15.75,66.28 15.31,66.73 12.21,66.73 12.01,66.92 12.01,67.24 12.13,67.36 15.25,67.36 16.26,68.36 16.26,69.51 16.5,69.75 19.04,69.75 19.23,69.55 19.23,66.74 19.63,66.34 28.67,66.34 28.97,66.64 28.97,67.06 28.67,67.36 20.23,67.36 20.1,67.49 20.1,67.68 20.23,67.82 28.67,67.82 28.97,68.12 28.97,68.54 28.67,68.83 20.23,68.83 20.1,68.97 20.1,69.16 20.23,69.29 29.62,69.29 30.33,68.58 30.33,67.88 29.77,67.32 29.77,66.57 30.31,66.03 31.15,66.03 31.8,66.67 31.8,67.34 31.95,67.49 32.21,67.49 v2(32.56,67.13)
DCLKP: length 88.2
  BOTTOM w0.152: v2(16.71,67.64) 17.04,67.64 17.81,68.4 18.26,68.4 18.77,67.89 18.77,66.58 18.33,66.14 17.42,66.14 15.53,64.24 11.93,64.24 11.66,64.52 11.66,65.07 11.94,65.35 15.09,65.35 15.47,65.74 15.47,66.17 15.19,66.45 12.09,66.45 11.73,66.8 11.73,67.36 12.01,67.64 15.14,67.64 15.98,68.48 15.98,69.62 16.38,70.03 19.15,70.03 19.51,69.67 19.51,66.85 19.74,66.62 28.56,66.62 28.69,66.76 28.69,66.95 28.56,67.08 20.12,67.08 19.82,67.38 19.82,67.8 20.12,68.1 28.56,68.1 28.69,68.23 28.69,68.42 28.56,68.55 20.12,68.55 19.82,68.85 19.82,69.27 20.12,69.57 29.73,69.57 30.61,68.7 30.61,67.77 30.05,67.21 30.05,66.69 30.43,66.31 31.04,66.31 31.52,66.79 31.52,67.41 v2(31.29,67.64)
EXT_LFN: length 9.1
  TOP w0.152: C55.1 C52.1 62.81,122.9 62.81,120.73 63.78,119.76 63.78,116.53 U2.41
EXT_LFP: length 5.7
  TOP w0.152: C55.2 64.74,121 R48.1 64.21,120.47 U2.40
EXTIO: length 70.4
  TOP w0.152: 89.79,116.31 TP2.1
  BOTTOM w0.102: U1.G12 49.2,67.84 49.58,68.22 50.67,68.22 50.68,68.23 50.71,68.23 50.97,68.5
  BOTTOM w0.152: 50.97,68.5 51.89,69.42 51.89,71.35 53.59,73.05 53.59,73.13 71.02,90.55 71.02,91.03 86.18,106.2 90.6,106.2 91.72,107.31 91.72,111.96 TP2.1
FIFO-OSTR: length 20.5
  TOP w0.152: R71.1 60.6,102.68 60.6,101.22 59.87,100.48 58.62,100.48 55.75,103.35 53.85,103.35 51.94,101.45 C100.1 ; R68.2 60.58,104.35 60.58,104.72 61.7,105.84 61.7,107.5 62.1,107.9 62.1,109.3 U2.17
  TOP w0.305: R68.2 R71.1
FIFO-OSTRC: length 20.4
  TOP w0.152: U2.16 61.8,109.32 61.8,108.03 61.39,107.62 61.39,105.97 60.27,104.85 60.27,104.38 59.9,104.01 59.9,104.01 R69.2 ; C99.1 51.77,101.71 53.72,103.66 55.88,103.66 58.75,100.79 59.74,100.79 60.3,101.35 60.3,102.59 R72.1
  TOP w0.305: R69.2 R72.1
FIFO_ISTRN: length 51.8
  TOP w0.127: 40.03,67.14 U1.H1
  TOP w0.152: v2(14.93,49.51) 14.96,49.48 15.48,49.48 15.82,49.82 15.82,50.07 19.55,53.8 19.91,53.8 20.19,53.52 20.19,52.8 20.46,52.53 20.85,52.53 21.13,52.8 21.13,54.96 21.24,55.07 21.4,55.07 21.51,54.96 21.51,52.8 21.79,52.53 22.17,52.53 22.45,52.8 22.45,54.96 22.56,55.07 22.72,55.07 22.83,54.96 22.83,52.8 23.11,52.53 23.5,52.53 23.77,52.8 23.77,54.96 23.88,55.07 24.04,55.07 24.15,54.96 24.15,52.8 24.43,52.53 24.82,52.53 25.09,52.8 25.09,54.96 25.2,55.07 25.36,55.07 25.47,54.96 25.47,54.24 25.86,53.85 26.63,53.85 39.93,67.14 40.03,67.14
  BOTTOM w0.152: J13.178 14.91,49.53 v2(14.93,49.51)
FIFO_ISTRP: length 52.5
  TOP w0.127: U1.H2 40.7,67.04 40.3,67.43 39.98,67.43 39.97,67.42
  TOP w0.152: 39.97,67.42 39.81,67.42 26.52,54.13 25.98,54.13 25.75,54.36 25.75,55.07 25.48,55.35 25.09,55.35 24.81,55.07 24.81,52.92 24.7,52.81 24.54,52.81 24.43,52.92 24.43,55.07 24.16,55.35 23.77,55.35 23.49,55.07 23.49,52.92 23.38,52.81 23.22,52.81 23.11,52.92 23.11,55.07 22.84,55.35 22.45,55.35 22.17,55.07 22.17,52.92 22.06,52.81 21.9,52.81 21.79,52.92 21.79,55.07 21.51,55.35 21.12,55.35 20.85,55.07 20.85,52.92 20.74,52.81 20.58,52.81 20.47,52.92 20.47,53.63 20.03,54.08 19.43,54.08 v2(15.37,50.01)
  BOTTOM w0.152: 13.9,49.99 15.35,49.99 v2(15.37,50.01) ; 13.9,49.99 13.9,50.01 J13.176 ; 13.9,49.99 13.88,50.01
FIFO_OSTR: length 19.7
  TOP w0.152: R152.1 46.37,79.49 46.37,80.66 41.96,85.06 41.96,91.57 42.29,91.9 R90.1 ; U6.16 45.44,94.94 43.59,93.1 R89.2
  TOP w0.305: R90.1 R89.2
FIFO_OSTRC: length 19.9
  TOP w0.152: R92.1 42.16,92.16 41.68,91.68 41.68,84.95 46.09,80.54 46.09,79.53 45.72,79.16 R149.1 ; U6.15 45.24,95.15 43.42,93.33 R91.2
  TOP w0.305: R91.2 R92.1
FPGA_CLKOUT2_N: length 65.2
  TOP w0.152: R93.1 49.1,112.83 v2(48.72,112.83)
  BOTTOM w0.152: v2(48.72,112.83) 48.56,112.98 47.22,112.98 39.4,105.16 39.4,100.63 37.01,98.25 28.65,98.25 24.51,94.11 24.51,93.62 24.22,93.32 23.8,93.32 23.61,93.51 23.42,93.51 23.28,93.37 23.28,93.18 23.47,92.99 23.47,92.57 23.17,92.28 22.75,92.28 22.56,92.47 22.38,92.47 22.24,92.33 22.24,92.14 22.43,91.95 22.43,91.53 22.13,91.23 21.71,91.23 21.52,91.42 21.33,91.42 21.2,91.29 21.2,91.1 21.39,90.91 21.39,90.49 21.09,90.19 20.67,90.19 20.48,90.38 20.29,90.38 20.1,90.19 20.1,89.7 18.8,88.39 12.63,88.39 11.86,89.16 11.86,95.62 11.31,96.16 9.7,96.16 9.22,95.68 8.85,95.68 8.81,95.65 8.77,95.65 8.66,95.54 J13.33
FPGA_CLKOUT2_P: length 65.2
  TOP w0.152: v2(48.72,113.51) 49.12,113.51 R88.1
  BOTTOM w0.152: v2(48.72,113.51) 48.46,113.26 47.1,113.26 39.12,105.27 39.12,100.75 36.89,98.53 28.54,98.53 24.23,94.22 24.23,94.04 24.23,93.73 24.1,93.6 23.91,93.6 23.72,93.79 23.3,93.79 23,93.49 23,93.07 23.19,92.88 23.19,92.69 23.06,92.56 22.87,92.56 22.68,92.74 22.26,92.74 21.96,92.45 21.96,92.03 22.15,91.84 22.15,91.65 22.02,91.51 21.83,91.51 21.64,91.7 21.22,91.7 20.92,91.4 20.92,90.98 21.11,90.8 21.11,90.61 20.97,90.47 20.79,90.47 20.6,90.66 20.18,90.66 19.82,90.3 19.82,90.24 19.82,90.07 19.82,89.81 18.68,88.67 12.74,88.67 12.14,89.27 12.14,95.73 11.43,96.44 9.59,96.44 9.1,95.96 8.72,95.96 8.65,96.04 J13.31
FPGA_CLKOUTN: length 65.1
  TOP w0.152: v2(48.97,108.33) 49.19,108.33 49.42,108.1 50.01,108.1 R117.2
  BOTTOM w0.152: v2(48.97,108.33) 48.97,108.23 48.08,107.35 48.08,106.33 37.92,96.16 31.74,96.16 22.34,86.77 14.43,86.77 11.99,84.33 11.99,70.41 12.75,69.65 13.77,69.65 13.88,69.54 J13.118
FPGA_CLKOUTP: length 65.2
  TOP w0.152: v2(49.61,108.56) 49.53,108.64 49.53,109.04 49.68,109.19 49.89,109.19 50.11,108.97 R116.2
  BOTTOM w0.152: v2(49.61,108.56) 49.58,108.53 49.58,108 49.43,107.85 49,107.85 48.98,107.85 48.36,107.23 48.36,106.21 38.04,95.89 31.85,95.89 22.45,86.49 14.54,86.49 12.27,84.21 12.27,70.52 12.87,69.92 13.77,69.92 13.88,70.04 J13.116
GC_+6.0VDC: length 163
  TOP w0.152: 13.92,104.22 13.88,104.18 v2(13.88,103.55)
  TOP w1.524: 6.63,104.19 6.63,103.4 6.83,103.4 ; 6.63,104.19 v2(6.96,104.19) C143.1 ; 6.63,104.19 6.63,104.67 C143.1 ; 6.83,103.4 7.57,104.14 ; 6.83,103.4 7.72,102.51 7.85,102.51 ; C143.1 7.57,104.39 7.57,104.14 ; 7.57,104.14 v2(7.85,104.14) 7.85,102.51 ; 15.11,103.4 14.83,103.68 14.83,104.11 14.73,104.22 13.92,104.22 ; 15.11,103.4 14.22,102.51 13.92,102.51 ; 15.11,103.4 15.11,103.81 C144.1 13.92,104.22 ; 13.92,104.22 13.92,102.51 ; 7.85,102.51 13.92,102.51
  L3_PWR w1.524: 13.92,104.22 14.02,104.11 14.83,104.11 15.11,103.84 15.11,103.4 13.94,103.4 13.26,102.72 9.27,102.72 v2(7.85,104.14) 7.8,104.19 v2(6.96,104.19) 6.96,103.73 6.63,103.4
  L6_PWR w1.524: 15.11,103.4 14.83,103.68 14.83,104.11 14.73,104.22 13.92,104.22 13.92,103.35 13.28,102.72 9.27,102.72 v2(7.85,104.14) 7.8,104.19 v2(6.96,104.19) 6.96,103.73 6.63,103.4
  L6_PWR w2.032: JP10.3 32.39,27.53 32.39,39.62 27.56,44.45 5.08,44.45 3.18,46.36 3.18,99.9 6.63,103.35 6.63,103.4
  BOTTOM w0.254: 6.96,103.55 6.96,103.05 J13.3 J13.1 ; J13.4 v2(13.88,103.55)
  BOTTOM w0.508: 7.8,104.19 v2(6.96,104.19) 6.96,103.55 J13.1 7.85,103.55 v2(7.85,104.14) 7.01,104.14
  vias: v2(6.99,105.16) v2(7.42,103.56) v2(13.84,105.16) v2(13.84,104.32)
IO_LOGIC: length 28.3
  TOP w0.381: v2(97.75,111.14) 97.75,109.76 C250.1
  BOTTOM w0.102: 47.72,73.08 47.72,66.05 47.95,65.82 48.3,65.82 48.52,65.59 48.52,64.97 48.85,64.64 U1.L12
  BOTTOM w0.152: 47.72,73.08 47.93,73.29 47.93,76.5 v2(48.13,76.71)
  BOTTOM w0.254: U4.7 96.11,119.96 v2(96.44,120.29) ; U4.10 v2(96.91,118) ; U5.10 v2(103.67,118.1) ; U5.7 102.87,119.94 v2(103.17,120.24) ; v2(96.47,117.5) 96.11,117.86 U4.1
  BOTTOM w0.381: U9.14 v2(98.84,123.57) ; U3.4 v2(97.75,111.14)
  BOTTOM w0.508: C142.1 v2(97.92,124.05) ; C98.1 v2(91.95,128.32) ; U20.4 v2(113.18,108.69) C138.2 v2(111.91,108.69) ; 110.36,109.7 v2(110.36,109.25) ; R136.1 v2(109.73,109.7) ; C94.1 v2(96.6,120.98) ; R46.2 v2(87.17,126.31) ; R73.1 v2(106.43,118.77) ; R83.1 v2(95.83,125.07) ; U10.5 v2(91.99,127.68) ; R74.1 v2(95.83,128.12) ; R137.1 v2(108.56,109.7) ; C140.1 v2(103.3,120.98)
IOUTA1: length 28.7
  TOP w0.152: C284.1 63.88,89.28 61.91,89.28 59.82,87.19 59.82,81.58 53.64,75.41 53.64,72.16 53.09,71.6 52.65,71.6 R112.1 52.32,71.58 50.8,71.58 U1.B14
  TOP w0.305: C284.1 C281.2 L41.2
IOUTA2: length 28.7
  TOP w0.152: U1.C14 50.57,71.04 50.83,71.3 52.35,71.3 R98.1 52.68,71.32 53.2,71.32 53.92,72.05 53.92,75.3 60.1,81.47 60.1,87.07 62.03,89 63.91,89 C278.2
  TOP w0.305: C278.2 C281.1 L40.2
IOUTB1: length 28.7
  TOP w0.152: C269.2 63.83,76.25 61.46,76.25 60.56,75.36 60.56,75.17 60.69,75.04 60.69,74.62 60.39,74.32 59.97,74.32 59.41,74.88 59.23,74.88 59.09,74.75 59.09,74.56 59.65,74 59.65,73.58 59.35,73.28 58.93,73.28 58.37,73.84 58.18,73.84 58.05,73.71 58.05,73.52 58.61,72.96 58.61,72.54 58.31,72.24 57.89,72.24 57.33,72.8 57.14,72.8 57.01,72.66 57.01,72.48 57.57,71.92 57.57,71.5 57.27,71.2 56.85,71.2 56.29,71.76 56.1,71.76 55.97,71.62 55.97,71.43 56.52,70.87 56.52,70.45 56.23,70.16 55.81,70.16 55.25,70.72 55.06,70.72 54.92,70.58 54.92,70.39 55.05,70.26 55.05,69.84 54.1,68.9 53.43,68.9 R97.1 53.1,68.9 50.8,68.9 50.54,68.64 U1.F14
  TOP w0.305: C269.2 C272.1 L36.2
IOUTB2: length 28.6
  TOP w0.152: U1.E14 50.8,69.18 53.1,69.18 R96.1 53.43,69.18 53.99,69.18 54.77,69.96 54.77,70.15 54.64,70.28 54.64,70.7 54.94,70.99 55.36,70.99 55.92,70.44 56.11,70.44 56.24,70.57 56.24,70.76 55.69,71.32 55.69,71.74 55.98,72.04 56.4,72.04 56.96,71.48 57.15,71.48 57.29,71.61 57.29,71.8 56.73,72.36 56.73,72.78 57.03,73.08 57.45,73.08 58,72.52 58.19,72.52 58.33,72.65 58.33,72.84 57.77,73.4 57.77,73.82 58.07,74.12 58.49,74.12 59.05,73.56 59.24,73.56 59.37,73.7 59.37,73.88 58.81,74.44 58.81,74.86 59.11,75.16 59.53,75.16 60.09,74.6 60.28,74.6 60.41,74.74 60.41,74.93 60.29,75.05 60.29,75.47 61.34,76.53 63.96,76.53 C275.1
  TOP w0.305: L37.2 C272.2 C275.1
IOUTC1: length 28.6
  TOP w0.152: U1.J14 50.8,65.98 53.1,65.98 R94.1 53.43,65.98 54.04,65.98 54.88,65.14 55.07,65.14 55.19,65.26 55.62,65.26 55.91,64.97 55.91,64.54 55.35,63.99 55.35,63.8 55.49,63.66 55.68,63.66 56.24,64.22 56.66,64.22 56.95,63.92 56.95,63.5 56.4,62.94 56.4,62.76 56.53,62.62 56.72,62.62 57.28,63.18 57.7,63.18 58,62.88 58,62.46 57.44,61.9 57.44,61.71 57.57,61.58 57.76,61.58 58.32,62.14 58.74,62.14 59.04,61.84 59.04,61.42 58.48,60.86 58.48,60.67 58.61,60.54 58.8,60.54 59.36,61.1 59.78,61.1 60.08,60.8 60.08,60.38 59.52,59.82 59.52,59.63 59.66,59.5 59.85,59.5 59.97,59.62 60.39,59.62 61.32,58.7 63.91,58.7 64.26,59.05
  TOP w0.305: 64.26,59.05 C263.2 L34.2
IOUTC2: length 28.6
  TOP w0.152: U1.K14 50.54,65.44 50.8,65.7 53.1,65.7 R41.1 53.43,65.7 53.92,65.7 54.76,64.86 55.18,64.86 55.31,64.98 55.5,64.98 55.63,64.85 55.63,64.66 55.07,64.1 55.07,63.68 55.37,63.38 55.79,63.38 56.35,63.94 56.54,63.94 56.68,63.81 56.68,63.62 56.12,63.06 56.12,62.64 56.41,62.34 56.84,62.34 57.39,62.9 57.58,62.9 57.72,62.77 57.72,62.58 57.16,62.02 57.16,61.6 57.46,61.3 57.88,61.3 58.44,61.86 58.62,61.86 58.76,61.72 58.76,61.54 58.2,60.98 58.2,60.56 58.5,60.26 58.92,60.26 59.48,60.82 59.67,60.82 59.8,60.68 59.8,60.49 59.24,59.93 59.24,59.51 59.54,59.22 59.96,59.22 60.09,59.34 60.28,59.34 61.2,58.42 63.88,58.42 C261.2
  TOP w0.305: C261.2 C263.1 L31.2
IOUTD1: length 28.7
  TOP w0.152: C251.2 63.88,45.59 61.81,45.59 60.4,47 60.4,53.19 53.59,59.99 53.59,62.69 52.98,63.3 52.68,63.3 R35.1 52.32,63.3 50.8,63.3 U1.N14
  TOP w0.305: C251.2 C255.1 L27.2
IOUTD2: length 28.7
  TOP w0.152: C258.1 63.91,45.87 61.93,45.87 60.68,47.12 60.68,53.3 53.87,60.11 53.87,62.8 53.1,63.58 52.65,63.58 R33.1 52.35,63.58 50.8,63.58 U1.M14
  TOP w0.305: L29.2 C255.2 C258.1
PARITYN: length 52
  BOTTOM w0.127: U1.P8 45.74,61.6
  BOTTOM w0.152: J13.172 13.88,51.01 14,51.13 14.91,51.13 v2(15.03,51.01) 15.57,51.01 15.93,50.66 15.93,47.79 19.11,44.6 20.31,44.6 21.15,45.44 21.34,45.44 21.47,45.31 21.47,44.82 21.77,44.53 22.19,44.53 22.49,44.82 22.49,45.31 22.62,45.44 22.81,45.44 22.95,45.31 22.95,44.82 23.24,44.53 23.66,44.53 23.96,44.82 23.96,45.31 24.1,45.44 24.28,45.44 24.42,45.31 24.42,44.82 24.72,44.53 25.14,44.53 25.43,44.82 25.43,45.31 25.57,45.44 25.76,45.44 25.89,45.31 25.89,45.28 26.19,44.98 35.31,44.98 42.42,52.1 42.42,55.12 45.74,58.44 45.74,61.6
PARITYP: length 52.5
  BOTTOM w0.127: 45.46,61.65 45.35,61.77 45.35,62.64 U1.N8
  BOTTOM w0.152: J13.170 15.45,51.53 v2(15.47,51.51) 16.21,50.77 16.21,47.9 19.23,44.88 20.2,44.88 21.03,45.72 21.45,45.72 21.75,45.42 21.75,44.94 21.89,44.81 22.08,44.81 22.21,44.94 22.21,45.42 22.51,45.72 22.93,45.72 23.22,45.42 23.22,44.94 23.36,44.81 23.55,44.81 23.68,44.94 23.68,45.42 23.98,45.72 24.4,45.72 24.7,45.42 24.7,44.94 24.83,44.81 25.02,44.81 25.16,44.94 25.16,45.42 25.45,45.72 25.87,45.72 26.17,45.42 26.17,45.4 26.31,45.26 35.19,45.26 42.14,52.21 42.14,55.23 45.46,58.55 45.46,61.65
PLLAVDD: length 10.8
  TOP w1.016: v2(58.78,70.76) 58.88,70.87 TP26.1 61.01,70.03 v2(60.07,70.03) v2(58.75,70.03)
  BOTTOM w0.305: C49.1 v2(47.35,73.63)
  BOTTOM w1.016: FB1.1 58.85,70.13 v2(58.75,70.03) ; FB1.1 v2(58.78,70.76) ; FB1.1 59.97,70.13 v2(60.07,70.03) ; FB1.1 59.41,70.15 ; 59.41,70.15 v2(60.02,70.76) ; 59.41,70.15 59.41,70.74 v2(59.39,70.76)
SCLK: length 138.7
  BOTTOM w0.152: U1.P9 46.54,62.12 49.23,59.44 52.15,59.44 54.94,62.23 62.23,62.23 75.31,75.31 76.2,75.31 87.53,86.64 89.66,86.64 92.35,89.33 92.35,92.35 101.24,101.24 116.13,101.24 119,104.11 119,113.92 116.38,116.54 116.38,124.92 104.04,137.26 101.7,137.26 JP9.1
SDENB: length 141.2
  BOTTOM w0.102: 47.45,61.77 47.34,61.88 U1.P10
  BOTTOM w0.152: 47.45,61.77 49.35,59.87 51.92,59.87 54.76,62.71 61.93,62.71 75.56,76.35 76.45,76.35 87.27,87.17 89.53,87.17 91.9,89.53 91.9,92.68 101.02,101.8 115.9,101.8 118.49,104.39 118.49,113.67 115.8,116.36 115.8,124.84 103.86,136.78 101.85,136.78 100.97,135.89 100.97,134.49 100.46,133.99 97.28,133.99 96.22,135.05 JP12.1
SDIO: length 140.2
  BOTTOM w0.102: U1.P11 48.14,61.77
  BOTTOM w0.152: JP13.1 92.91,135.05 94.41,133.55 100.71,133.55 101.47,134.32 101.47,135.76 101.98,136.27 103.76,136.27 115.32,124.71 115.32,115.95 117.91,113.36 117.91,104.65 115.57,102.31 100.76,102.31 61.62,63.17 54.66,63.17 51.77,60.27 49.53,60.27 48.14,61.67 48.14,61.77
SDO: length 124.7
  BOTTOM w0.102: U1.P12 48.94,61.77
  BOTTOM w0.152: JP8.1 104.17,135.13 114.81,124.49 114.81,115.7 117.35,113.16 117.35,104.8 115.39,102.84 100.63,102.84 61.44,63.65 54.41,63.65 51.44,60.68 49.73,60.68 48.94,61.47 48.94,61.77
SLEEP: length 68.6
  BOTTOM w0.102: 51,64.22 48.78,64.22 48.56,64 48.56,63.46 U1.N11
  BOTTOM w0.152: 51,64.22 51.06,64.16 51.76,64.16 52.04,64.44 52.04,64.85 53.87,66.67 53.87,72.85 71.17,90.14 72.26,90.14 74.68,92.56 74.68,93.57 76.2,95.1 76.94,95.1 85.85,104.01 90.25,104.01 92.96,106.73 JP3.2
SPI_CLK: length 32.2
  TOP w0.152: U2.24 65.71,109.02 v2(66.8,107.92)
  BOTTOM w0.152: R85.2 91.77,119.56 84.66,119.56 73.03,107.92 v2(66.8,107.92)
SPI_LE: length 40.5
  TOP w0.152: v2(98.27,119.86) 97.69,119.28 97.52,119.28 97.26,119.01 97.26,118.34 97.38,118.21 97.38,115.09 94.44,112.14 83.85,112.14 80.42,108.71 67.39,108.71 66.48,109.62 U2.25
  BOTTOM w0.152: R139.2 v2(98.27,119.86)
SPI_MISO: length 43.8
  TOP w0.152: U2.22 64.71,108.5 65.72,107.48 65.72,107.47 66,107.19 79.65,107.19 84.1,111.63 94.62,111.63 98.55,115.57 99.52,115.57 100.15,116.2 100.15,117.04 v2(98.93,118.26)
  BOTTOM w0.152: R140.2 v2(98.93,118.26)
SPI_MOSI: length 33
  TOP w0.152: U2.23 65.21,108.76 v2(66.03,107.94)
  BOTTOM w0.152: v2(66.03,107.94) 66.52,107.44 73.13,107.44 84.79,119.1 91.82,119.1 R138.2
SYNCN: length 60.1
  TOP w0.152: v1(12.55,53.87) 12.32,53.64 12.32,53.21 R157.2
  L6_PWR w0.127: v1(12.55,53.87) 12.27,54.15 12.27,74.88 15.37,77.98 40.22,77.98 44.88,73.32 44.88,73.31 45.34,72.84 45.34,72.48 45.74,72.08 U1.B8
SYNCP: length 60.1
  TOP w0.152: v1(11.68,54.53) 11.89,54.33 11.89,53.6 12.01,53.47 12.01,53.16 R156.2
  L6_PWR w0.127: U1.A8 45.74,72.8 45.13,73.41 45.13,73.43 40.32,78.23 15.27,78.23 12.01,74.98 12.01,54.71 11.84,54.53 v1(11.68,54.53)
TCXO_VCC: length 16.8
  TOP w0.508: C181.1 55.23,136.88 FB25.1 ; C181.1 53.33,135.48 C178.1 C182.1 R165.2 v2(50.04,136.09) ; C181.1 53.58,132.16 54.49,131.25 U17.8
  BOTTOM w0.508: U16.9 50.04,132.16 v2(50.04,136.09)
TEST: length 81.2
  BOTTOM w0.102: 46.91,73.08 46.92,73.07 46.92,69.28 46.66,69.02 46.38,69.02 46.16,68.79 46.16,66.08 46.38,65.86 46.74,65.86 46.94,65.66 46.94,65.28 47.16,65.06 47.57,65.06 47.99,64.64 U1.L11
  BOTTOM w0.152: 46.91,73.08 46.86,73.13 46.86,76.2 48.79,78.13 57.12,78.13 69.09,90.09 70,90.09 70.46,90.55 70.46,91.26 85.8,106.6 90.27,106.6 91.03,107.37 91.03,111.23 90.3,111.96 87.66,111.96 TP4.1
TXENABLE: length 70.7
  BOTTOM w0.102: U1.N9 46.12,63.46 46.12,64.79 45.9,65.02 45.58,65.02 45.32,65.28 45.32,73.07 45.31,73.08
  BOTTOM w0.152: JP2.2 86.11,107.65 56.95,78.49 48.54,78.49 45.31,75.26 45.31,73.08
USB RESET: length 27.1
  TOP w0.152: v2(101.65,107.42) 101.73,107.42 103.58,109.27 103.58,114.66 108.2,119.28 C50.1 108.2,120.09 110.68,122.57 SW2.4
  TOP w0.508: SW2.3 SW2.4
  BOTTOM w0.152: U3.19 v2(101.65,107.42)
VBB: length 3.8
  TOP w0.305: v2(48.35,101.43) 47.56,100.64 47.56,99.04 U6.6
  BOTTOM w0.305: R70.2 48.84,100.95 v2(48.35,101.43)
N24210609: length 5.6
  TOP w0.305: L28.1 C253.2 C254.1 73.41,45.11 74.32,44.2 R7.1 R6.2 R104.1
N26666012: length 10
  TOP w0.127: U1.H12 48.9,67.04 48.55,66.68 48.55,60.18 48.16,59.79 v2(48.16,57.86)
  BOTTOM w0.152: R44.1 48.18,57.89 v2(48.16,57.86)
